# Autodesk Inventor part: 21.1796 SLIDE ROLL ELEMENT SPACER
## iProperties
Created: 2007-05
Part Number: 21.1796 SLIDE ROLL ELEMENT SPACER
Material: Aluminum-6061
Document SubType Name: Modeling
Designer: Andy Moles
Mass: 0.536364 g
Surface Area: 4.68097 cm^2
Volume: 0.19792 cm^3
Density: 2.71 g/cm^3
Author: Andy Moles
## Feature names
1. Extrusion1
